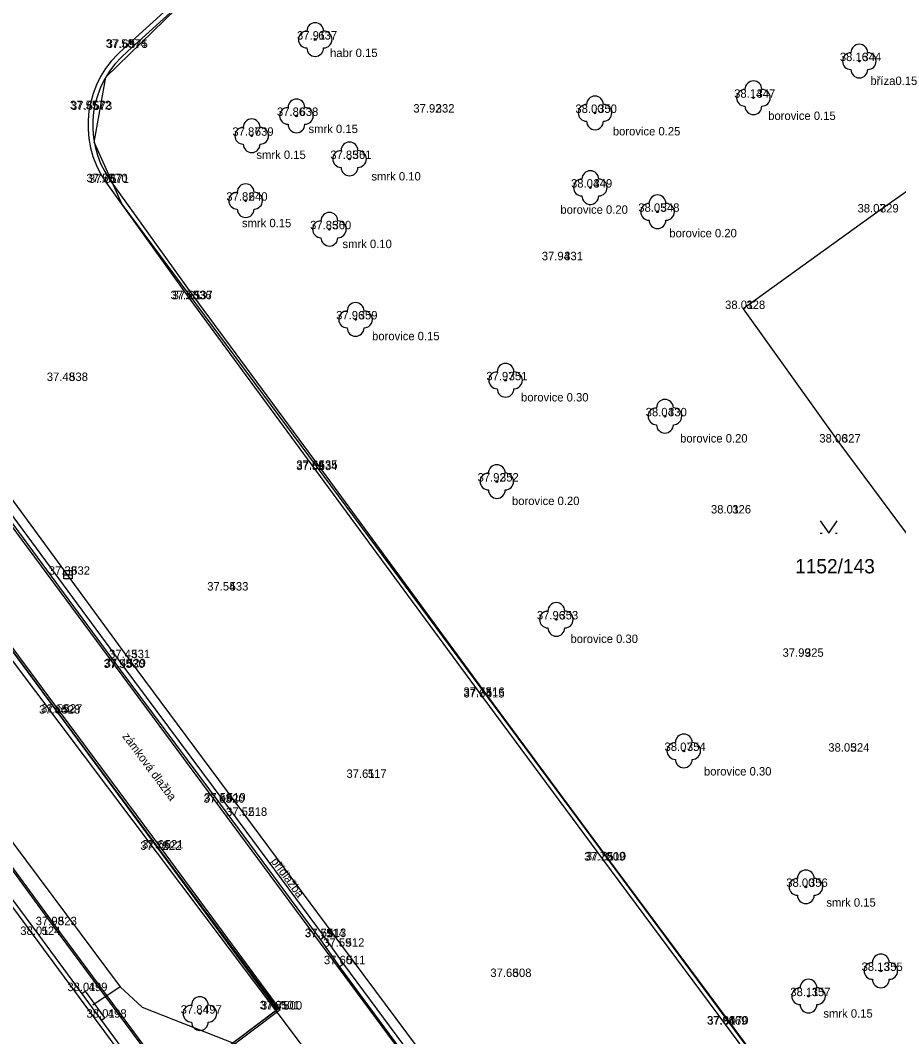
# Model space of a CAD drawing. Extents: x -609709 to -609357, y -1051535 to -1051131.
# Drawn here: x -609570.23 to -609544.11, y -1051331.13 to -1051300.92 of the extents above; entities that cross this region are included whole.
import ezdxf

# ---------------------------------------------------------------- set-up
doc = ezdxf.new("R2010")
doc.units = 0
for name, color, linetype in [('Vrstva 1', 7, 'Continuous'), ('Vrstva 10', 7, 'Continuous'), ('Vrstva 12', 7, 'Continuous'), ('Vrstva 2', 7, 'Continuous'), ('Vrstva 3', 7, 'Continuous'), ('Vrstva 4', 7, 'Continuous'), ('Vrstva 5', 7, 'Continuous'), ('Vrstva 7', 7, 'Continuous'), ('Vrstva 9', 7, 'Continuous')]:
    doc.layers.add(name, color=color, linetype=linetype)

msp = doc.modelspace()

# ---------------------------------------------------------------- linework, layer by layer
at = {"layer": 'Vrstva 1'}
for p, q in [((-609561.46, -1051301.49), (-609561.46, -1051301.49)), ((-609567.12, -1051301.73), (-609567.12, -1051301.73)), ((-609567.09, -1051301.74), (-609567.09, -1051301.74)), ((-609545.28, -1051302.13), (-609545.28, -1051302.13)), ((-609548.43, -1051303.22), (-609548.43, -1051303.22)), ((-609568.18, -1051303.56), (-609568.18, -1051303.56)), ((-609568.15, -1051303.58), (-609568.15, -1051303.58)), ((-609562.02, -1051303.76), (-609562.02, -1051303.76)), ((-609557.97, -1051303.66), (-609557.97, -1051303.66)), ((-609553.14, -1051303.67), (-609553.14, -1051303.67)), ((-609563.35, -1051304.35), (-609563.35, -1051304.35)), ((-609560.44, -1051305.04), (-609560.44, -1051305.04)), ((-609567.69, -1051305.73), (-609567.69, -1051305.73)), ((-609567.65, -1051305.75), (-609567.65, -1051305.75)), ((-609553.28, -1051305.89), (-609553.28, -1051305.89)), ((-609563.53, -1051306.28), (-609563.53, -1051306.28)), ((-609551.28, -1051306.61), (-609551.28, -1051306.61)), ((-609544.76, -1051306.63), (-609544.76, -1051306.63)), ((-609561.04, -1051307.13), (-609561.04, -1051307.13)), ((-609554.15, -1051308.05), (-609554.15, -1051308.05)), ((-609565.19, -1051309.21), (-609565.19, -1051309.21)), ((-609565.16, -1051309.21), (-609565.16, -1051309.21)), ((-609548.73, -1051309.5), (-609548.73, -1051309.5)), ((-609560.26, -1051309.81), (-609560.26, -1051309.81)), ((-609568.87, -1051311.64), (-609568.87, -1051311.64)), ((-609555.8, -1051311.62), (-609555.8, -1051311.62)), ((-609551.06, -1051312.69), (-609551.06, -1051312.69)), ((-609545.89, -1051313.47), (-609545.89, -1051313.47)), ((-609561.45, -1051314.25), (-609561.45, -1051314.25)), ((-609561.45, -1051314.29), (-609561.45, -1051314.29)), ((-609556.06, -1051314.63), (-609556.06, -1051314.63)), ((-609549.15, -1051315.58), (-609549.15, -1051315.58)), ((-609568.81, -1051317.4), (-609568.81, -1051317.4)), ((-609564.1, -1051317.87), (-609564.1, -1051317.87)), ((-609554.29, -1051318.73), (-609554.29, -1051318.73)), ((-609567.02, -1051319.88), (-609567.02, -1051319.88)), ((-609546.99, -1051319.84), (-609546.99, -1051319.84)), ((-609567.18, -1051320.17), (-609567.18, -1051320.17)), ((-609567.15, -1051320.15), (-609567.15, -1051320.15)), ((-609556.48, -1051321), (-609556.48, -1051321)), ((-609556.48, -1051321.05), (-609556.48, -1051321.05)), ((-609569.1, -1051321.53), (-609569.1, -1051321.53)), ((-609569.04, -1051321.5), (-609569.04, -1051321.5)), ((-609550.5, -1051322.64), (-609550.5, -1051322.64)), ((-609545.63, -1051322.66), (-609545.63, -1051322.66)), ((-609559.99, -1051323.44), (-609559.99, -1051323.44)), ((-609564.21, -1051324.18), (-609564.21, -1051324.18)), ((-609564.18, -1051324.14), (-609564.18, -1051324.14)), ((-609563.54, -1051324.57), (-609563.54, -1051324.57)), ((-609566.03, -1051325.54), (-609566.03, -1051325.54)), ((-609566.09, -1051325.58), (-609566.09, -1051325.58)), ((-609552.89, -1051325.9), (-609552.89, -1051325.9)), ((-609552.87, -1051325.89), (-609552.87, -1051325.89)), ((-609546.87, -1051326.68), (-609546.87, -1051326.68)), ((-609569.2, -1051327.82), (-609569.2, -1051327.82)), ((-609569.69, -1051328.11), (-609569.69, -1051328.11)), ((-609561.23, -1051328.18), (-609561.23, -1051328.18)), ((-609561.19, -1051328.17), (-609561.19, -1051328.17)), ((-609560.65, -1051328.46), (-609560.65, -1051328.46)), ((-609560.62, -1051328.98), (-609560.62, -1051328.98)), ((-609555.68, -1051329.36), (-609555.68, -1051329.36)), ((-609544.64, -1051329.18), (-609544.64, -1051329.18)), ((-609568.29, -1051329.78), (-609568.29, -1051329.78)), ((-609546.79, -1051329.93), (-609546.79, -1051329.93)), ((-609562.57, -1051330.32), (-609562.57, -1051330.32)), ((-609562.5, -1051330.33), (-609562.5, -1051330.33)), ((-609567.72, -1051330.57), (-609567.72, -1051330.57)), ((-609564.89, -1051330.45), (-609564.89, -1051330.45)), ((-609549.26, -1051330.78), (-609549.26, -1051330.78)), ((-609549.23, -1051330.77), (-609549.23, -1051330.77))]:
    msp.add_line(p, q, dxfattribs=at)
at = {"layer": 'Vrstva 10'}
for p, q in [((-609567.69, -1051302.61), (-609564.36, -1051299.37)), ((-609581.79, -1051300.71), (-609506.66, -1051402.14)), ((-609568.03, -1051304.55), (-609567.69, -1051302.61)), ((-609568.03, -1051304.55), (-609567.21, -1051306.38)), ((-609567.21, -1051306.38), (-609543.5, -1051338.34)), ((-609575.82, -1051312.44), (-609562.6, -1051330.34)), ((-609546.44, -1051315.795), (-609546.19, -1051316.17)), ((-609546.19, -1051316.17), (-609545.94, -1051315.795)), ((-609546.44, -1051316.17), (-609546.39, -1051316.17)), ((-609545.99, -1051316.17), (-609545.94, -1051316.17)), ((-609572.88, -1051324.02), (-609566.22, -1051333.03)), ((-609566.22, -1051333.03), (-609562.6, -1051330.34))]:
    msp.add_line(p, q, dxfattribs=at)
at = {"layer": 'Vrstva 12'}
for points in [[(-609615.546, -1051325.052), (-609614.108, -1051326.974), (-609589.099, -1051308.266), (-609582.815, -1051303.565), (-609514.844, -1051393.856), (-609499.807, -1051382.785), (-609467.693, -1051377.467)], [(-609578.07, -1051315.17), (-609567.26, -1051329.65), (-609568.072, -1051330.196)], [(-609567.26, -1051329.65), (-609566.61, -1051330.26), (-609563.81, -1051331.36), (-609561.81, -1051332.78), (-609557.22, -1051340.25), (-609556.47, -1051344.07), (-609557.345, -1051344.694)]]:
    msp.add_lwpolyline(points, dxfattribs=at)
at = {"layer": 'Vrstva 4'}
for p, q in [((-609567.576, -1051305.649), (-609565.077, -1051309.128)), ((-609565.077, -1051309.128), (-609561.337, -1051314.207)), ((-609561.337, -1051314.207), (-609556.367, -1051320.967)), ((-609556.367, -1051320.967), (-609552.778, -1051325.817)), ((-609569.24, -1051327.85), (-609572.16, -1051323.88)), ((-609552.778, -1051325.817), (-609549.148, -1051330.697)), ((-609566.19, -1051331.97), (-609569.24, -1051327.85)), ((-609549.148, -1051330.697), (-609545.767, -1051335.267))]:
    msp.add_line(p, q, dxfattribs=at)
for points in [[(-609569.78, -1051291.945), (-609575.052, -1051295.767), (-609578.513, -1051298.267), (-609581.715, -1051300.651), (-609578.673, -1051304.783), (-609576.293, -1051308.002), (-609575.723, -1051308.802), (-609573.942, -1051311.224), (-609573.352, -1051312.004), (-609570.993, -1051315.183), (-609567.262, -1051320.233), (-609564.292, -1051324.224), (-609561.303, -1051328.252), (-609560.734, -1051329.062), (-609558.952, -1051331.474)], [(-609569.78, -1051291.945), (-609566.877, -1051295.877), (-609564.302, -1051299.348), (-609567.029, -1051301.836)], [(-609569.81, -1051292.14), (-609574.97, -1051295.88), (-609578.43, -1051298.38), (-609581.52, -1051300.68), (-609578.56, -1051304.7), (-609576.18, -1051307.92), (-609575.61, -1051308.72), (-609573.83, -1051311.14), (-609573.24, -1051311.92), (-609570.88, -1051315.1), (-609567.15, -1051320.15), (-609564.18, -1051324.14), (-609561.19, -1051328.17), (-609560.62, -1051328.98), (-609558.84, -1051331.39)], [(-609569.81, -1051292.14), (-609566.99, -1051295.96), (-609564.49, -1051299.33), (-609567.12, -1051301.73)], [(-609581.29, -1051300.49), (-609578.2, -1051304.72), (-609575.96, -1051307.74), (-609573.15, -1051311.54), (-609570.93, -1051314.56), (-609567.02, -1051319.88), (-609560.65, -1051328.46), (-609558.43, -1051331.45), (-609556.52, -1051334.05), (-609554.94, -1051336.21), (-609551.65, -1051340.58), (-609547.88, -1051345.71), (-609545.37, -1051349.12), (-609543.12, -1051352.14), (-609541.57, -1051354.24), (-609540.598, -1051355.492)], [(-609567.69, -1051305.73), (-609565.19, -1051309.21), (-609561.45, -1051314.29), (-609556.48, -1051321.05), (-609552.89, -1051325.9), (-609549.26, -1051330.78), (-609545.88, -1051335.35), (-609541.56, -1051341.2), (-609537.96, -1051338.59), (-609534.58, -1051336.17), (-609530.96, -1051333.54), (-609527.42, -1051330.97), (-609523.72, -1051328.34), (-609521.12, -1051326.49), (-609517.15, -1051323.61), (-609513.51, -1051320.93), (-609509.43, -1051317.99)], [(-609562.5, -1051330.33), (-609566.03, -1051325.54), (-609569.04, -1051321.5), (-609572.56, -1051316.74), (-609575.87, -1051312.27), (-609578.97, -1051314.54)], [(-609578.94, -1051314.61), (-609575.88, -1051312.34), (-609572.62, -1051316.75), (-609569.1, -1051321.53), (-609566.09, -1051325.58), (-609562.57, -1051330.32), (-609565.07, -1051332.2), (-609565.55, -1051331.51), (-609566.15, -1051331.94)], [(-609566.15, -1051331.94), (-609569.2, -1051327.82), (-609572.12, -1051323.85), (-609575.24, -1051319.63), (-609578.94, -1051314.61)], [(-609561.19, -1051328.17), (-609561.303, -1051328.252)], [(-609560.62, -1051328.98), (-609560.734, -1051329.062)], [(-609566.1, -1051331.98), (-609565.57, -1051331.57), (-609565.07, -1051332.26), (-609562.5, -1051330.33)]]:
    msp.add_lwpolyline(points, dxfattribs=at)
for radius, start, end in [(2.973, 129.0847, 214.6952), (2.833, 129.0042, 214.6709)]:
    msp.add_arc((-609565.246, -1051304.038), radius, start, end, dxfattribs=at)
at = {"layer": 'Vrstva 5'}
msp.add_line((-609568.935, -1051317.4), (-609568.685, -1051317.4), dxfattribs=at)
for points in [[(-609548.73, -1051309.5), (-609545.89, -1051313.47), (-609542.89, -1051317.51), (-609538.84, -1051314.77), (-609537.5, -1051316.78), (-609535.34, -1051315.33), (-609536.71, -1051313.31), (-609534.7, -1051311.86), (-609537.66, -1051307.78), (-609540.6, -1051303.71)], [(-609541.48, -1051304.32), (-609544.76, -1051306.63), (-609548.73, -1051309.5)]]:
    msp.add_lwpolyline(points, dxfattribs=at)
msp.add_lwpolyline([(-609568.935, -1051317.275), (-609568.685, -1051317.275), (-609568.685, -1051317.525), (-609568.935, -1051317.525)], close=True, dxfattribs=at)
at = {"layer": 'Vrstva 7'}
for centre in [(-609561.46, -1051301.49), (-609545.28, -1051302.13), (-609548.43, -1051303.22), (-609562.02, -1051303.76), (-609553.14, -1051303.67), (-609563.35, -1051304.35), (-609560.44, -1051305.04), (-609553.28, -1051305.89), (-609563.53, -1051306.28), (-609551.28, -1051306.61), (-609561.04, -1051307.13), (-609560.26, -1051309.81), (-609555.8, -1051311.62), (-609551.06, -1051312.69), (-609556.06, -1051314.63), (-609554.29, -1051318.73), (-609550.5, -1051322.64), (-609546.87, -1051326.68), (-609544.64, -1051329.18), (-609546.79, -1051329.93), (-609564.89, -1051330.45)]:
    msp.add_circle(centre, 0.025, dxfattribs=at)
for centre, start, end in [((-609561.46, -1051301.24), 0, 180), ((-609561.71, -1051301.49), 90, 270), ((-609561.21, -1051301.49), 270, 90), ((-609545.28, -1051301.88), 0, 180), ((-609561.46, -1051301.74), 180, 0), ((-609545.53, -1051302.13), 90, 270), ((-609545.03, -1051302.13), 270, 90), ((-609545.28, -1051302.38), 180, 0), ((-609548.43, -1051302.97), 0, 180), ((-609553.14, -1051303.42), 0, 180), ((-609548.68, -1051303.22), 90, 270), ((-609548.18, -1051303.22), 270, 90), ((-609562.02, -1051303.51), 0, 180), ((-609553.39, -1051303.67), 90, 270), ((-609552.89, -1051303.67), 270, 90), ((-609548.43, -1051303.47), 180, 0), ((-609562.27, -1051303.76), 90, 270), ((-609561.77, -1051303.76), 270, 90), ((-609563.35, -1051304.1), 0, 180), ((-609562.02, -1051304.01), 180, 0), ((-609553.14, -1051303.92), 180, 0), ((-609563.6, -1051304.35), 90, 270), ((-609563.1, -1051304.35), 270, 90), ((-609563.35, -1051304.6), 180, 0), ((-609560.44, -1051304.79), 0, 180), ((-609560.69, -1051305.04), 90, 270), ((-609560.19, -1051305.04), 270, 90), ((-609560.44, -1051305.29), 180, 0), ((-609553.28, -1051305.64), 0, 180), ((-609563.53, -1051306.03), 0, 180), ((-609553.53, -1051305.89), 90, 270), ((-609553.03, -1051305.89), 270, 90), ((-609563.78, -1051306.28), 90, 270), ((-609563.28, -1051306.28), 270, 90), ((-609553.28, -1051306.14), 180, 0), ((-609551.28, -1051306.36), 0, 180), ((-609551.53, -1051306.61), 90, 270), ((-609551.03, -1051306.61), 270, 90), ((-609563.53, -1051306.53), 180, 0), ((-609561.04, -1051306.88), 0, 180), ((-609561.29, -1051307.13), 90, 270), ((-609560.79, -1051307.13), 270, 90), ((-609551.28, -1051306.86), 180, 0), ((-609561.04, -1051307.38), 180, 0), ((-609560.26, -1051309.56), 0, 180), ((-609560.51, -1051309.81), 90, 270), ((-609560.01, -1051309.81), 270, 90), ((-609560.26, -1051310.06), 180, 0), ((-609555.8, -1051311.37), 0, 180), ((-609556.05, -1051311.62), 90, 270), ((-609555.55, -1051311.62), 270, 90), ((-609555.8, -1051311.87), 180, 0), ((-609551.06, -1051312.44), 0, 180), ((-609551.31, -1051312.69), 90, 270), ((-609550.81, -1051312.69), 270, 90), ((-609551.06, -1051312.94), 180, 0), ((-609556.06, -1051314.38), 0, 180), ((-609556.31, -1051314.63), 90, 270), ((-609555.81, -1051314.63), 270, 90), ((-609556.06, -1051314.88), 180, 0), ((-609554.29, -1051318.48), 0, 180), ((-609554.54, -1051318.73), 90, 270), ((-609554.04, -1051318.73), 270, 90), ((-609554.29, -1051318.98), 180, 0), ((-609550.5, -1051322.39), 0, 180), ((-609550.75, -1051322.64), 90, 270), ((-609550.25, -1051322.64), 270, 90), ((-609550.5, -1051322.89), 180, 0), ((-609547.12, -1051326.68), 90, 270), ((-609546.87, -1051326.43), 0, 180), ((-609546.62, -1051326.68), 270, 90), ((-609546.87, -1051326.93), 180, 0), ((-609544.64, -1051328.93), 0, 180), ((-609544.89, -1051329.18), 90, 270), ((-609544.39, -1051329.18), 270, 90), ((-609546.79, -1051329.68), 0, 180), ((-609544.64, -1051329.43), 180, 0), ((-609547.04, -1051329.93), 90, 270), ((-609546.54, -1051329.93), 270, 90), ((-609564.89, -1051330.2), 0, 180), ((-609565.14, -1051330.45), 90, 270), ((-609564.64, -1051330.45), 270, 90), ((-609546.79, -1051330.18), 180, 0), ((-609564.89, -1051330.7), 180, 0)]:
    msp.add_arc(centre, 0.25, start, end, dxfattribs=at)
at = {"layer": 'Vrstva 9'}
for points in [[(-609579.46, -1051314.88), (-609575.7, -1051319.98), (-609572.56, -1051324.24), (-609569.69, -1051328.11), (-609566.11, -1051332.97)], [(-609567.822, -1051330.645), (-609567.72, -1051330.57), (-609568.29, -1051329.78), (-609568.4, -1051329.861)]]:
    msp.add_lwpolyline(points, dxfattribs=at)

# ---------------------------------------------------------------- texts
at = {"layer": 'Vrstva 10'}
msp.add_text('1152/143', height=0.425, dxfattribs=at).set_placement((-609547.19, -1051317.36))
at = {"layer": 'Vrstva 2'}
for s, p in [(' 637', (-609561.46, -1051301.49)), (' 574', (-609567.12, -1051301.73)), (' 575', (-609567.09, -1051301.74)), (' 344', (-609545.28, -1051302.13)), (' 347', (-609548.43, -1051303.22)), (' 572', (-609568.18, -1051303.56)), (' 573', (-609568.15, -1051303.58)), (' 332', (-609557.97, -1051303.66)), (' 350', (-609553.14, -1051303.67)), (' 638', (-609562.02, -1051303.76)), (' 639', (-609563.35, -1051304.35)), (' 361', (-609560.44, -1051305.04)), (' 570', (-609567.69, -1051305.73)), (' 571', (-609567.65, -1051305.75)), (' 349', (-609553.28, -1051305.89)), (' 640', (-609563.53, -1051306.28)), (' 348', (-609551.28, -1051306.61)), (' 329', (-609544.76, -1051306.63)), (' 360', (-609561.04, -1051307.13)), (' 331', (-609554.15, -1051308.05)), (' 536', (-609565.19, -1051309.21)), (' 537', (-609565.16, -1051309.21)), (' 328', (-609548.73, -1051309.5)), (' 359', (-609560.26, -1051309.81)), (' 538', (-609568.87, -1051311.64)), (' 351', (-609555.8, -1051311.62)), (' 330', (-609551.06, -1051312.69)), (' 327', (-609545.89, -1051313.47)), (' 535', (-609561.45, -1051314.25)), (' 534', (-609561.45, -1051314.29)), (' 352', (-609556.06, -1051314.63)), (' 326', (-609549.15, -1051315.58)), (' 532', (-609568.81, -1051317.4)), (' 533', (-609564.1, -1051317.87)), (' 353', (-609554.29, -1051318.73)), (' 531', (-609567.02, -1051319.88)), (' 325', (-609546.99, -1051319.84)), (' 530', (-609567.18, -1051320.17)), (' 529', (-609567.15, -1051320.15)), (' 516', (-609556.48, -1051321)), (' 515', (-609556.48, -1051321.05)), (' 528', (-609569.1, -1051321.53)), (' 527', (-609569.04, -1051321.5)), (' 354', (-609550.5, -1051322.64)), (' 324', (-609545.63, -1051322.66)), (' 517', (-609559.99, -1051323.44)), (' 520', (-609564.21, -1051324.18)), (' 519', (-609564.18, -1051324.14)), (' 518', (-609563.54, -1051324.57)), (' 522', (-609566.09, -1051325.58)), (' 521', (-609566.03, -1051325.54)), (' 509', (-609552.89, -1051325.9)), (' 510', (-609552.87, -1051325.89)), (' 356', (-609546.87, -1051326.68)), (' 523', (-609569.2, -1051327.82)), (' 524', (-609569.69, -1051328.11)), (' 514', (-609561.23, -1051328.18)), (' 513', (-609561.19, -1051328.17)), (' 512', (-609560.65, -1051328.46)), (' 511', (-609560.62, -1051328.98)), (' 508', (-609555.68, -1051329.36)), (' 355', (-609544.64, -1051329.18)), (' 499', (-609568.29, -1051329.78)), (' 357', (-609546.79, -1051329.93)), (' 501', (-609562.57, -1051330.32)), (' 500', (-609562.5, -1051330.33)), (' 498', (-609567.72, -1051330.57)), (' 497', (-609564.89, -1051330.45)), (' 469', (-609549.26, -1051330.78)), (' 470', (-609549.23, -1051330.77))]:
    msp.add_text(s, height=0.25, dxfattribs=at).set_placement(p)
at = {"layer": 'Vrstva 3'}
for s, p in [('37.91', (-609562.002, -1051301.49)), ('37.58', (-609567.693, -1051301.73)), ('37.69', (-609567.663, -1051301.74)), ('38.16', (-609545.859, -1051302.13)), ('38.14', (-609549.003, -1051303.22)), ('37.55', (-609568.753, -1051303.56)), ('37.65', (-609568.723, -1051303.58)), ('37.92', (-609558.543, -1051303.66)), ('38.00', (-609553.723, -1051303.67)), ('37.86', (-609562.599, -1051303.76)), ('37.87', (-609563.923, -1051304.35)), ('37.85', (-609561.013, -1051305.04)), ('37.55', (-609568.263, -1051305.73)), ('37.61', (-609568.192, -1051305.75)), ('38.04', (-609553.853, -1051305.89)), ('37.82', (-609564.103, -1051306.28)), ('38.05', (-609551.853, -1051306.61)), ('38.07', (-609545.333, -1051306.63)), ('37.85', (-609561.613, -1051307.13)), ('37.94', (-609554.723, -1051308.05)), ('37.53', (-609565.763, -1051309.21)), ('37.61', (-609565.702, -1051309.21)), ('38.01', (-609549.272, -1051309.5)), ('37.96', (-609560.839, -1051309.81)), ('37.48', (-609569.443, -1051311.64)), ('37.97', (-609556.373, -1051311.62)), ('38.04', (-609551.633, -1051312.69)), ('38.06', (-609546.469, -1051313.47)), ('37.55', (-609562.023, -1051314.29)), ('37.64', (-609562.023, -1051314.25)), ('37.92', (-609556.633, -1051314.63)), ('38.01', (-609549.692, -1051315.58)), ('37.38', (-609569.383, -1051317.4)), ('37.54', (-609564.673, -1051317.87)), ('37.96', (-609554.869, -1051318.73)), ('37.43', (-609567.593, -1051319.88)), ('37.99', (-609547.563, -1051319.84)), ('37.55', (-609567.753, -1051320.17)), ('37.43', (-609567.723, -1051320.15)), ('37.73', (-609557.053, -1051321)), ('37.64', (-609557.053, -1051321.05)), ('37.64', (-609569.673, -1051321.53)), ('37.59', (-609569.613, -1051321.5)), ('38.07', (-609551.073, -1051322.64)), ('38.05', (-609546.203, -1051322.66)), ('37.61', (-609560.532, -1051323.44)), ('37.63', (-609564.783, -1051324.18)), ('37.50', (-609564.763, -1051324.14)), ('37.52', (-609564.113, -1051324.57)), ('37.72', (-609566.663, -1051325.58)), ('37.66', (-609566.609, -1051325.54)), ('37.72', (-609553.463, -1051325.9)), ('37.81', (-609553.412, -1051325.89)), ('38.00', (-609547.453, -1051326.68)), ('37.98', (-609569.773, -1051327.82)), ('38.01', (-609570.232, -1051328.11)), ('37.71', (-609561.772, -1051328.18)), ('37.59', (-609561.763, -1051328.17)), ('37.59', (-609561.223, -1051328.46)), ('37.60', (-609561.203, -1051328.98)), ('37.68', (-609556.253, -1051329.36)), ('38.13', (-609545.213, -1051329.18)), ('38.01', (-609568.832, -1051329.78)), ('38.11', (-609547.332, -1051329.93)), ('37.81', (-609563.112, -1051330.32)), ('37.75', (-609563.073, -1051330.33)), ('38.01', (-609568.262, -1051330.57)), ('37.84', (-609565.463, -1051330.45)), ('37.90', (-609549.813, -1051330.77)), ('37.81', (-609549.802, -1051330.78))]:
    msp.add_text(s, height=0.25, dxfattribs=at).set_placement(p)
at = {"layer": 'Vrstva 4'}
for s, rotation, p in [('zámková dlažba', 306.6879, (-609567.211, -1051322.208)), ('přídlažba', 306.5911, (-609562.791, -1051325.924))]:
    msp.add_text(s, height=0.25, rotation=rotation, dxfattribs=at).set_placement(p)
at = {"layer": 'Vrstva 7'}
for s, p in [('habr 0.15', (-609561.02, -1051302.01)), ('bříza0.15', (-609544.95, -1051302.84)), ('borovice 0.15', (-609547.99, -1051303.88)), ('smrk 0.15', (-609561.66, -1051304.27)), ('borovice 0.25', (-609552.61, -1051304.34)), ('smrk 0.15', (-609563.21, -1051305.04)), ('smrk 0.10', (-609559.79, -1051305.68)), ('borovice 0.20', (-609554.17, -1051306.67)), ('smrk 0.15', (-609563.64, -1051307.07)), ('borovice 0.20', (-609550.93, -1051307.37)), ('smrk 0.10', (-609560.65, -1051307.69)), ('borovice 0.15', (-609559.77, -1051310.43)), ('borovice 0.30', (-609555.34, -1051312.25)), ('borovice 0.20', (-609550.61, -1051313.47)), ('borovice 0.20', (-609555.61, -1051315.33)), ('borovice 0.30', (-609553.87, -1051319.43)), ('borovice 0.30', (-609549.9, -1051323.37)), ('smrk 0.15', (-609546.26, -1051327.27)), ('smrk 0.15', (-609546.35, -1051330.57))]:
    msp.add_text(s, height=0.25, dxfattribs=at).set_placement(p)

doc.saveas('drawing.dxf')
